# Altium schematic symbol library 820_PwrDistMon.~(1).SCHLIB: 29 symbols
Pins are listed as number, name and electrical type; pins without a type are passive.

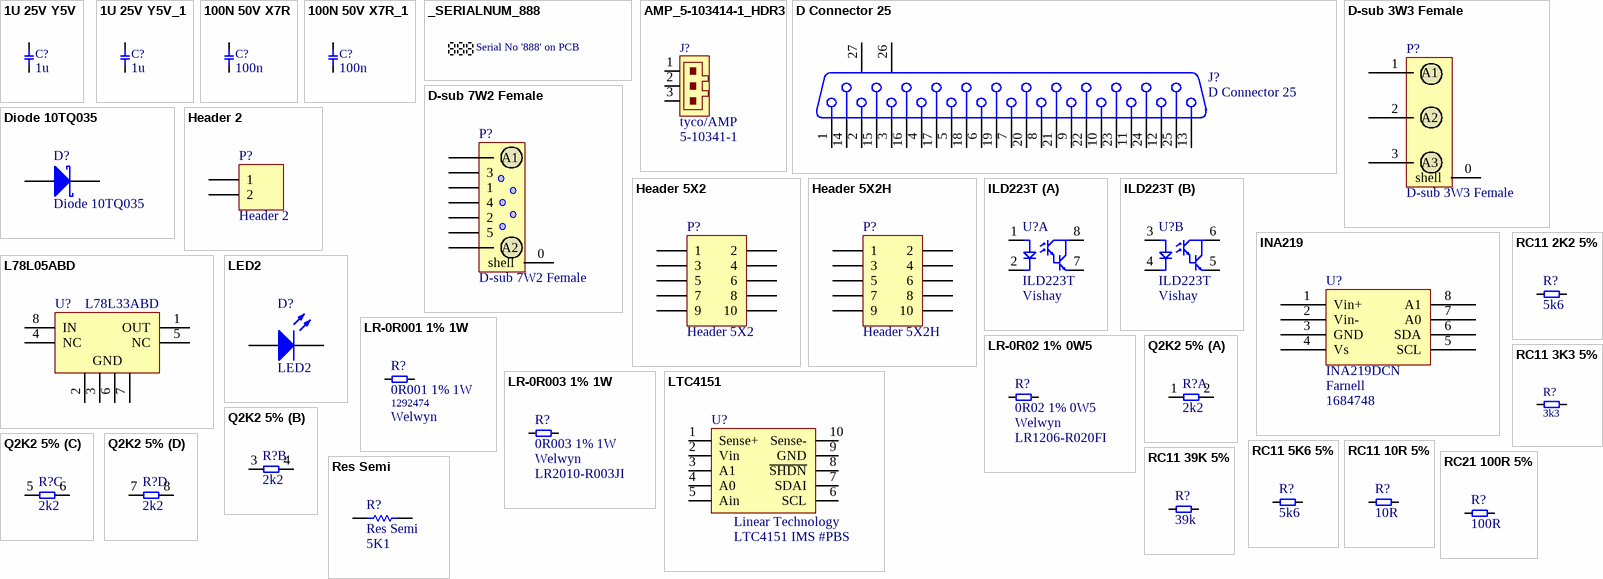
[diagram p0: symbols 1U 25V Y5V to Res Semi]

## 1U 25V Y5V
designator C?, comment 1u
1uF 25V Y5V -20+80%; Part Number: 1216536; Text Field3: Farnell; Text Field4: 317640; Text Field7: AVX; Text Field8: CM21Y5V105Z25VAT; Multiples: 1; $/qty: 0.161
footprint 0805
pins: 1, 2

## 1U 25V Y5V_1
designator C?, comment 1u
1uF 25V Y5V -20+80%; Part Number: 1216536; Text Field3: Farnell; Text Field4: 317640; Text Field7: AVX; Text Field8: CM21Y5V105Z25VAT; Multiples: 1; $/qty: 0.161
footprint 0805
pins: 1, 2

## 100N 50V X7R
designator C?, comment 100n
100nF X7R CMC 10%; Text Field1: AVX; Text Field2: CM21X7R104K50VAT; Text Field3: Farnell; Text Field4: 499687; Multiples: 1; $/qty: .05
footprint 0805
pins: 1, 2

## 100N 50V X7R_1
designator C?, comment 100n
100nF X7R CMC 10%; Text Field1: AVX; Text Field2: CM21X7R104K50VAT; Text Field3: Farnell; Text Field4: 499687; Multiples: 1; $/qty: .05
footprint 0805
pins: 1, 2

## _SERIALNUM_888
designator S/N?  (value not drawn)  (no BOM)
Serial Number '888' on PCB
footprint SERIAL_NUM_888

## AMP_5-103414-1_HDR3
designator J?  Manufacturer: tyco/AMP  Part Number: 5-10341-1  (hidden comment: AMP_5-103414-1_HDR3)
3 pin SIL 2.54mm Mod II Vertical Shrouded Header; Text Field3: Farnell; Text Field4: 1056042; Text Field5: 3.06; Text Field6: 1; Text Field8: mates with AMP 102241-1 , Field 5 is 1st col 2007 price ea, 6 is MOQ
footprint AMP_5-103414-1
pins: 1, 2, 3

## D Connector 25
designator J?
Receptacle Assembly, 25 Position, Right Angle; PackageDocument: U; Positions: 25
footprint DSUB1.385-2H25A (Connector; D Subminiature; 25 Position; Right Angle; Pitch 1.385 mm)
signal-integrity model Connector
pins: 1, 2, 3, 4, 5, 6, 7, 8, 9, 10, 11, 12, 13, 14, 15, 16, 17, 18, 19, 20, 21, 22, 23, 24, 25, 26 MH1, 27 MH2

## D-sub 3W3 Female
designator P?
signal-integrity model Connector
footprint Harting D-sub 3W3 Female Connector - duplicate (Harting D-sub 3W3 Female 3way 20A LP)
pins: 0 shell, 1 A1, 2 A2, 3 A3

## D-sub 7W2 Female
designator P?
signal-integrity model Connector
footprint Harting D-sub 7W2 Female Connector (Harting D-sub 7W2 Female 7way 5A LP)
pins: 0 shell, 1, 2, 3, 4, 5, 6 A1, 7 A2

## Diode 10TQ035
designator D?
Schottky Rectifier; Note: Terminal 2 is the TAB and is electrically connected to the cathode
footprint SFM-T2(3)/X1.7V (TO, Thru-Hole, Vertical, Heatsink Mounted; 3 In-Line Leads (1 Absent); Pitch 2.54 mm)
simulation model 10TQ035 (DIODE)
pins: 1 K, 3 A

## Header 2
designator P?
Header, 2-Pin
footprint HDR1X2 (Connector; Header; 2 Position)
signal-integrity model Connector
pins: 1, 2

## Header 5X2
designator P?
Header, 5-Pin, Dual row
footprint HDR2X5 (Connector; Header; 5x2 Position)
signal-integrity model Connector
pins: 1, 2, 3, 4, 5, 6, 7, 8, 9, 10

## Header 5X2H
designator P?
Header, 5-Pin, Dual row, Right Angle
footprint HDR2X5H (Connector; Header; 5x2 Position; Right Angle)
signal-integrity model Connector
pins: 1, 2, 3, 4, 5, 6, 7, 8, 9, 10

## ILD223T
designator U?  Manufacturer: Vishay
Dual Darlington smt Optocoupler; Text Field3: Farnell; Text Field4: 143480; Text Field7: CTR 500% @ 1mA, 15/30us ton/toff, 2k5V; Text Field8: .\CadLib\sc\.opto.ddb; Multiples: 1
footprint SOIC8-VISHAY
part A pins: 1, 2, 7, 8
part B pins: 3, 4, 5, 6

## INA219
designator U?, comment INA219DCN  Supplier 1: Farnell  Supplier Part Number 1: 1684748
Texas Instruments INA219 V/I monitor with I2C interface
footprint CN_R-PDSO-G8
pins: 1 Vin+, 2 Vin-, 3 GND, 4 Vs, 5 SCL, 6 SDA, 7 A0, 8 A1

## L78L05ABD
designator U?, comment L78L33ABD
Positive Voltage Regulator
footprint SO8_N (SOIC, 8-Leads, Body 4.9x3.9mm, Pitch 1.27mm, IPC Medium Density)
footprint SO8_L (SOIC, 8-Leads, Body 4.9x3.9mm, Pitch 1.27mm, IPC High Density)
footprint SO8_M (SOIC, 8-Leads, Body 4.9x3.9mm, Pitch 1.27mm, IPC Low Density)
3D model SO8 (8-Pin Small Outline Integrated Circuit 1.27 mm Pitch)
pins: 1 OUT (power), 2 GND (power), 3 GND (power), 4 NC, 5 NC, 6 GND (power), 7 GND (power), 8 IN (power)

## LED2
designator D?
Typical RED, GREEN, YELLOW, AMBER GaAs LED
footprint 3.2X1.6X1.1 (SMT LED; 2 Flat Leads)
simulation model LED2 (Diode)
pins: 1 A, 2 K

## LR-0R001 1% 1W
designator R?, comment 0R001 1% 1W  Part Number: 1292474  Manufacturer: Welwyn
1mOhms 1.0W ±100ppm/K 1%; Text Field2: ULR1-R001FT2; Multiples: 1; $/qty: 0.93
footprint WSL2010-18
pins: 1, 2

## LR-0R02 1% 0W5
designator R?, comment 0R02 1% 0W5  Manufacturer: Welwyn  Part Number: LR1206-R020FI
20 mOhms 0.5W ±100ppm/K 1%; Text Field3: Farnell; Text Field4: 1099909; Text Field5: 1.15; Text Field6: 5; Text Field8: Field 5 is Farnell 2009 $ea, 6 is MOQ; Multiples: 1; $/qty: 0.93
footprint 1206
pins: 1, 2

## LR-0R003 1% 1W
designator R?, comment 0R003 1% 1W  Manufacturer: Welwyn  Part Number: LR2010-R003JI
3mOhms 1.0W ±100ppm/K 1%; Part Number: 1100341; Multiples: 1; $/qty: 0.93
footprint WSL2010-18
pins: 1, 2

## LTC4151
designator U?  Manufacturer: Linear Technology  Part Number: LTC4151 IMS #PBS  (hidden comment: LTC4151)
7-80V High side current and voltage monitor, I2C with normal SDA; Text Field2: LTC4151IMS-1#PBF , LTC4151IDD-1#PBF; Text Field4: LTC4151IMS#PBF , LTC4151IDD#PBF; Text Field5: 5.57; Text Field6: 1; Text Field7: DD10 has an 11th pin - connect to Gnd; MSOP10 doesn't have it; Text Field8: Sensor.lib; 'I' is industrial temp range, can also get commercial 'C' type; field 5 is USD/unit; 6 is unit; Comments: US Dollars
footprint MSOP10 (LinearTech plastic MSOP10 ref dwg# 05-08-1661)
footprint DD10
pins: 1 Sense+, 2 Vin, 3 A1, 4 A0, 5 Ain, 6 SCL, 7 SDAI, 8 ~{SHDN}, 9 GND, 10 Sense-

## Q2K2 5%
designator R?, comment 2k2
2k25% 0.063W; Text Field1: Phycomp; Text Field2: 2350 034 10222; Text Field3: Farnell; Text Field4: 9241272; Text Field5: 0.22; Text Field6: 1; Text Field7: 7C1W2
footprint Q0603
part A pins: 1, 2
part B pins: 3, 4
part C pins: 5, 6
part D pins: 7, 8

## RC11 2K2 5%
designator R?, comment 5k6
2k2 5% 0.125W; Text Field1: Phicomp; Text Field2: 2322 730 61222; Text Field3: Farnell; Text Field4: 196319; Text Field6: 150V 0.125W; Multiples: 1
footprint 0805
pins: 1, 2

## RC11 3K3 5%
designator R?, comment 3k3
3k3 5% 0.125W; Text Field1: Phycomp; Text Field2: 2322 730 61332; Text Field3: Farnell; Text Field4: 9234071; Text Field5: 0.08; Text Field6: 1; Text Field7: 50
footprint 0805
pins: 1, 2

## RC11 5K6 5%
designator R?, comment 5k6
5k6 5% 0.125W; Text Field1: Phicomp; Text Field2: 2322 730 61562; Text Field3: Farnell; Text Field4: 196368; Text Field6: 150V 0.125W; Multiples: 1
footprint 0805
pins: 1, 2

## RC11 10R 5%
designator R?, comment 10R
10R 5% 0.125W; Text Field1: Phycomp; Text Field2: RC0805JR-0710RL; Text Field3: Farnell; Text Field4: 9233768; Text Field6: 150V 0.125W; Multiples: 1
footprint 0805
pins: 1, 2

## RC11 39K 5%
designator R?, comment 39k
39k 5% 0.125W; Text Field1: Phycomp; Text Field2: 2322 730 61393; Text Field3: Farnell; Text Field4: 9234209; Multiples: 1; $/qty: 0.08
footprint 0805
pins: 1, 2

## RC21 100R 5%
designator R?, comment 100R
100R 5% 0.1W; Part Number: 2322 730 61101; Part Number: 9233881; Text Field1: Phycomp; Text Field2: 2322 702 60101; Text Field3: Farnell; Text Field4: 9233235; Multiples: 1; $/qty: 0.08
footprint 0603
pins: 1, 2

## Res Semi
designator R?  value 5K1
Semiconductor Resistor
footprint AXIAL-0.5 (Semiconductor Resistor; 2 Leads)
footprint 1005[0402] (Chip Resistor; Body 1.1 x 0.5 mm (LxW typ))
footprint 1608[0603] (Chip Resistor; Body 1.6 x 0.8 mm (LxW typ))
footprint 2012[0805] (Chip Resistor; Body 2.0 x 1.3 mm (LxW typ))
footprint 3216[1206] (Chip Resistor; Body 3.2 x 1.6 mm (LxW typ))
simulation model RES (Semiconductor Resistor)
signal-integrity model Res Semi
pins: 1, 2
